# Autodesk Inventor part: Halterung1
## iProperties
Author: ketill
Created: 2002-11
Part Number: Halterung1
Material: Standard
Document SubType Name: Modellieren
Designer: ketill
Control State: 0
Master: False
Checked Out: False
PropertySet Name: Design Tracking Control
Shininess: 20.0
Angle Display Precision: 2
Document Length Units: 11269
Document Angle Units: 11283
Document Time Units: 11279
Document Mass Units: 11290
Document Length Units Precision: 3
Document Angle Units Precision: 2
Compacted: False
PropertySet Name: _Private Model Information
Density: 0.0
Volumn: 0.0
Area: 0.0
PropertySet Name: Model Information
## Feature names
1. Extrusion1
2. Bohrung1 [Hole]
